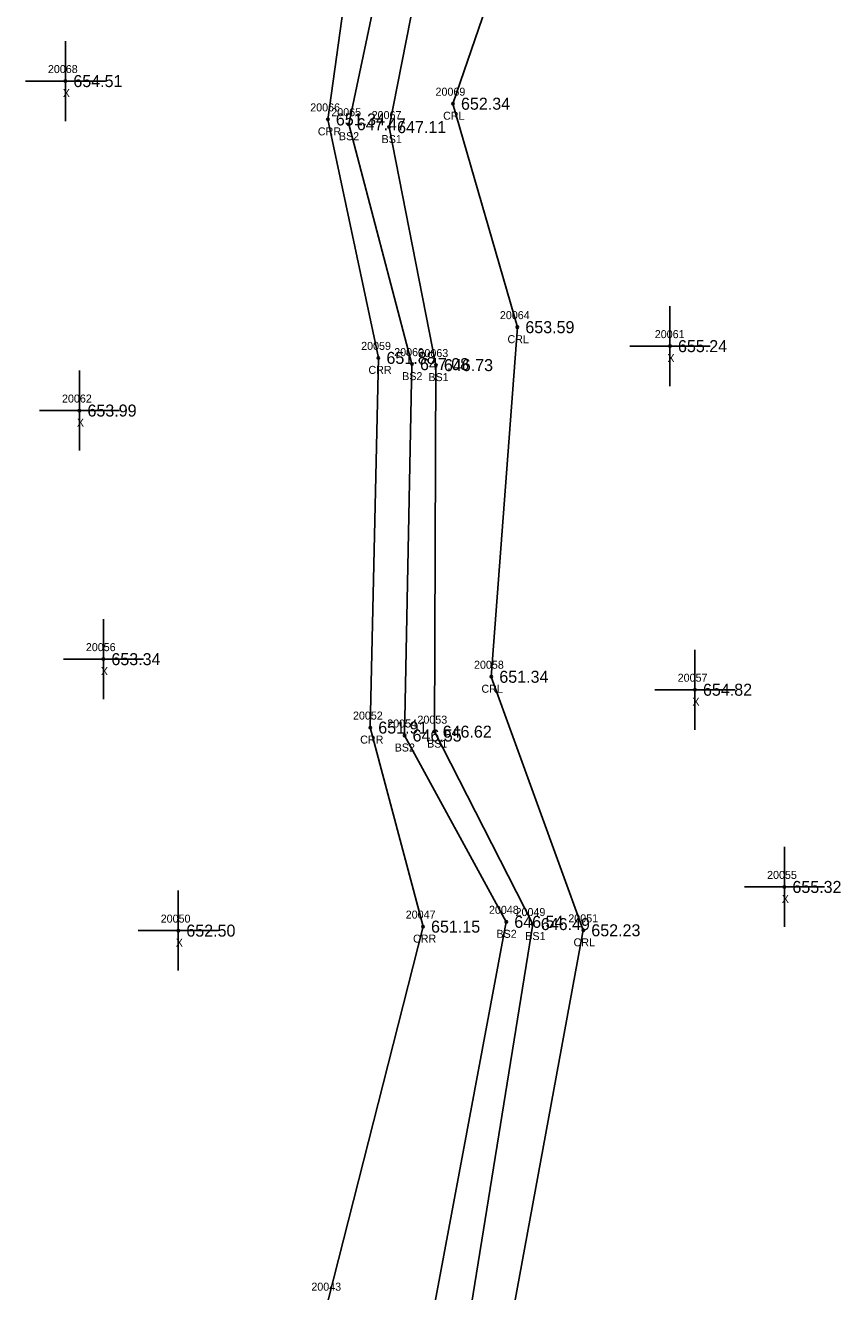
# Model space of a CAD drawing. Extents: x 1655675 to 1657082, y 1004080 to 1005193.
# Drawn here: x 1656358.8 to 1656460.6, y 1004891.3 to 1005049.5 of the extents above; entities that cross this region are included whole.
import ezdxf

# ---------------------------------------------------------------- set-up
doc = ezdxf.new("R2010")
doc.units = 0
for name, color, linetype in [('RD_DTM_BkLn2', 7, 'Continuous'), ('RD_DTM_BkLn_txCode', 7, 'Continuous'), ('RD_EX_H2O', 7, 'Continuous'), ('RD_EX_H2O_txCode', 7, 'Continuous'), ('RD_EX_Misc', 7, 'Continuous'), ('RD_EX_Misc_txCode', 7, 'Continuous'), ('RD_EX_TX_H2O_ELEV', 7, 'Continuous'), ('RD_EX_TX_Misc_ELEV', 7, 'Continuous'), ('RD_SMD_Locator', 7, 'Continuous')]:
    doc.layers.add(name, color=color, linetype=linetype)

msp = doc.modelspace()

# ---------------------------------------------------------------- linework, layer by layer
at = {"layer": 'RD_DTM_BkLn2'}
for points in [[(1656390.72, 1004627.52), (1656382.97, 1004639.34), (1656373.07, 1004660.2), (1656376.96, 1004698.66), (1656386.88, 1004718.9), (1656381.04, 1004756.9), (1656388.26, 1004792), (1656390.04, 1004832.88), (1656413.02, 1004880.46), (1656422.17, 1004937.24), (1656409.91, 1004961.28), (1656410.07, 1005007.08), (1656404.22, 1005036.82), (1656413.87, 1005085.9), (1656434.1, 1005133.63), (1656432.64, 1005179.28)], [(1656378.15, 1004634.61), (1656371.17, 1004659.81), (1656372.69, 1004701.15), (1656384.23, 1004720.35), (1656377.68, 1004756.93), (1656385.56, 1004794.36), (1656385.16, 1004833.8), (1656408.06, 1004879.84), (1656418.86, 1004937.52), (1656406.15, 1004960.8), (1656407.08, 1005007.2), (1656399.18, 1005037.18), (1656409.22, 1005084.89)]]:
    msp.add_lwpolyline(points, dxfattribs=at)
at = {"layer": 'RD_EX_H2O'}
for points in [[(1656396.09, 1004633.07), (1656383.79, 1004647.24), (1656376.78, 1004660.97), (1656381.31, 1004695.03), (1656390.77, 1004716.64), (1656386.6, 1004756.66), (1656392.47, 1004790.44), (1656395.46, 1004834.73), (1656418.17, 1004880.53), (1656428.48, 1004936.46), (1656416.99, 1004968.14), (1656420.24, 1005011.82), (1656412.2, 1005039.74), (1656428.37, 1005086.9), (1656442.1, 1005137.22), (1656437.49, 1005175.75)], [(1656368.16, 1004641.29), (1656363.88, 1004666), (1656364.85, 1004699.99), (1656373.08, 1004726.71), (1656370.55, 1004754.49), (1656376.9, 1004793.18), (1656381.94, 1004832.3), (1656396.67, 1004890.43), (1656408.46, 1004936.92), (1656401.87, 1004961.79), (1656402.89, 1005007.98), (1656396.57, 1005037.78), (1656403.09, 1005084.85)]]:
    msp.add_lwpolyline(points, dxfattribs=at)
at = {"layer": 'RD_EX_Misc'}
for p, q in [((1656363.78, 1005037.57), (1656363.78, 1005047.57)), ((1656358.78, 1005042.57), (1656368.78, 1005042.57)), ((1656439.31, 1005004.45), (1656439.31, 1005014.45)), ((1656434.31, 1005009.45), (1656444.31, 1005009.45)), ((1656365.54, 1004996.4), (1656365.54, 1005006.4)), ((1656360.54, 1005001.4), (1656370.54, 1005001.4)), ((1656368.53, 1004965.34), (1656368.53, 1004975.34)), ((1656442.43, 1004961.52), (1656442.43, 1004971.52)), ((1656363.53, 1004970.34), (1656373.53, 1004970.34)), ((1656437.43, 1004966.52), (1656447.43, 1004966.52)), ((1656453.6, 1004936.88), (1656453.6, 1004946.88)), ((1656377.89, 1004931.42), (1656377.89, 1004941.42)), ((1656448.6, 1004941.88), (1656458.6, 1004941.88)), ((1656372.89, 1004936.42), (1656382.89, 1004936.42))]:
    msp.add_line(p, q, dxfattribs=at)
at = {"layer": 'RD_SMD_Locator'}
for centre in [(1656363.78, 1005042.57), (1656412.2, 1005039.74), (1656396.57, 1005037.78), (1656399.18, 1005037.18), (1656404.22, 1005036.82), (1656420.24, 1005011.82), (1656439.31, 1005009.45), (1656402.89, 1005007.98), (1656407.08, 1005007.2), (1656410.07, 1005007.08), (1656365.54, 1005001.4), (1656368.53, 1004970.34), (1656416.99, 1004968.14), (1656442.43, 1004966.52), (1656401.87, 1004961.79), (1656406.15, 1004960.8), (1656409.91, 1004961.28), (1656453.6, 1004941.88), (1656377.89, 1004936.42), (1656408.46, 1004936.92), (1656418.86, 1004937.52), (1656422.17, 1004937.24), (1656428.48, 1004936.46)]:
    msp.add_circle(centre, 0.15, dxfattribs=at)

# ---------------------------------------------------------------- texts
at = {"layer": 'RD_DTM_BkLn_txCode'}
for s, p in [('20065', (1656397, 1005038.18)), ('20067', (1656402.04, 1005037.82)), ('BS2', (1656397.95, 1005035.18)), ('BS1', (1656403.28, 1005034.82)), ('20060', (1656404.86, 1005008.2)), ('20063', (1656407.89, 1005008.08)), ('BS2', (1656405.85, 1005005.2)), ('BS1', (1656409.13, 1005005.08)), ('20054', (1656403.99, 1004961.8)), ('20053', (1656407.76, 1004962.28)), ('BS1', (1656408.97, 1004959.28)), ('BS2', (1656404.92, 1004958.8)), ('20048', (1656416.7, 1004938.52)), ('20049', (1656420.02, 1004938.24)), ('BS2', (1656417.63, 1004935.52)), ('BS1', (1656421.23, 1004935.24))]:
    msp.add_text(s, height=1, dxfattribs=at).set_placement(p)
at = {"layer": 'RD_EX_H2O_txCode'}
for s, p in [('20069', (1656410.02, 1005040.74)), ('20066', (1656394.37, 1005038.78)), ('CRL', (1656410.97, 1005037.74)), ('CRR', (1656395.32, 1005035.78)), ('20064', (1656418.06, 1005012.82)), ('20059', (1656400.73, 1005008.98)), ('CRL', (1656419.01, 1005009.82)), ('CRR', (1656401.64, 1005005.98)), ('20058', (1656414.83, 1004969.14)), ('CRL', (1656415.76, 1004966.14)), ('20052', (1656399.71, 1004962.79)), ('CRR', (1656400.61, 1004959.79)), ('20047', (1656406.3, 1004937.92)), ('20051', (1656426.61, 1004937.46)), ('CRR', (1656407.21, 1004934.92)), ('CRL', (1656427.26, 1004934.46)), ('20043', (1656394.51, 1004891.43))]:
    msp.add_text(s, height=1, dxfattribs=at).set_placement(p)
at = {"layer": 'RD_EX_Misc_txCode'}
for s, p in [('20068', (1656361.6, 1005043.57)), ('X', (1656363.46, 1005040.57)), ('20061', (1656437.41, 1005010.45)), ('X', (1656438.99, 1005007.45)), ('20062', (1656363.36, 1005002.4)), ('X', (1656365.22, 1004999.4)), ('20056', (1656366.34, 1004971.34)), ('X', (1656368.21, 1004968.34)), ('20057', (1656440.27, 1004967.52)), ('X', (1656442.11, 1004964.52)), ('20055', (1656451.44, 1004942.88)), ('X', (1656453.28, 1004939.88)), ('20050', (1656375.69, 1004937.42)), ('X', (1656377.57, 1004934.42))]:
    msp.add_text(s, height=1, dxfattribs=at).set_placement(p)
at = {"layer": 'RD_EX_TX_H2O_ELEV'}
for s, p in [('652.34', (1656413.2, 1005038.99)), ('651.34', (1656397.57, 1005037.03)), ('653.59', (1656421.24, 1005011.07)), ('651.88', (1656403.89, 1005007.23)), ('651.34', (1656417.99, 1004967.39)), ('651.91', (1656402.87, 1004961.04)), ('651.15', (1656409.46, 1004936.17)), ('652.23', (1656429.48, 1004935.71))]:
    msp.add_text(s, height=1.5, dxfattribs=at).set_placement(p)
at = {"layer": 'RD_EX_TX_Misc_ELEV'}
for s, p in [('654.51', (1656364.78, 1005041.82)), ('647.47', (1656400.18, 1005036.43)), ('647.11', (1656405.22, 1005036.07)), ('655.24', (1656440.31, 1005008.7)), ('647.08', (1656408.08, 1005006.45)), ('646.73', (1656411.07, 1005006.33)), ('653.99', (1656366.54, 1005000.65)), ('653.34', (1656369.53, 1004969.59)), ('654.82', (1656443.43, 1004965.77)), ('646.62', (1656410.91, 1004960.53)), ('646.55', (1656407.15, 1004960.05)), ('655.32', (1656454.6, 1004941.13)), ('646.54', (1656419.86, 1004936.77)), ('652.50', (1656378.89, 1004935.67)), ('646.49', (1656423.17, 1004936.49))]:
    msp.add_text(s, height=1.5, dxfattribs=at).set_placement(p)

doc.saveas('drawing.dxf')
